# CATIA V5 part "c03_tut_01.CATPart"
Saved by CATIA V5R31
Part number: c03tut1
Bounding box of the stored display mesh (mm): x -1 to 1, y -100 to 100, z -100 to 100
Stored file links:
  D:\PROJECTS\Project 2021\US EDITION\CATIA V5 6R 2021\Resources\Tutorial Files\c03_catia_v5_6r2021_tut\c03_tut_01.CATPart
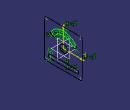
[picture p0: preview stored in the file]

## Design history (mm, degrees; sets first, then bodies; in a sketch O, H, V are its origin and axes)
Body1 (main body)
  Sketch1 on yz-plane, origin (0, 0, 0), H (0, 1, 0), V (0, 0, 1)
    line L1 (100, 90) -> (100, -90)
    line L2 (90, -100) -> (-90, -100)
    line L3 (-100, -90) -> (-100, 90)
    line L4 (-90, 100) -> (90, 100)
    arc A1 centre (90, 90) radius 10 from (100, 90) to (90, 100) ccw
    arc A2 centre (-90, 90) radius 10 from (-100, 90) to (-90, 100) cw
    arc A3 centre (90, -90) radius 10 from (100, -90) to (90, -100) cw
    arc A4 centre (-90, -90) radius 10 from (-90, -100) to (-100, -90) cw
    circle A5 centre (0, 0) radius 20
    construction line L5 (-70, -70) -> (70, -70)
    line L6 (-70, -60) -> (70, -60)
    line L7 (70, -80) -> (-70, -80)
    arc A6 centre (70, -70) radius 10 from (70, -60) to (70, -80) cw
    arc A7 centre (-70, -70) radius 10 from (-70, -80) to (-70, -60) cw
    construction arc A8 centre (0, 0) radius 70 from (57.3406, 40.1504) to (-57.3406, 40.1504) ccw
    construction line L8 (0, 0) -> (57.3406, 40.1504)
    construction line L9 (0, 0) -> (-57.3406, 40.1504)
    arc A9 centre (57.3406, 40.1504) radius 10 from (65.5322, 45.8861) to (49.1491, 34.4146) cw
    arc A10 centre (-57.3406, 40.1504) radius 10 from (-49.1491, 34.4146) to (-65.5322, 45.8861) cw
    arc A11 centre (0, 0) radius 60 from (49.1491, 34.4146) to (-49.1491, 34.4146) ccw
    arc A12 centre (0, 0) radius 80 from (-65.5322, 45.8861) to (65.5322, 45.8861) cw
    radius A1 = 10
    radius A2 = 10
    radius A3 = 10
    radius A4 = 10
    distance L5 L6 = 10
    radius A8 = 70
    angle L8 L9 = 110
    radius A10 = 10
    vertical: L1 V, L3 V
    horizontal: L2 H, L4 H, L5 H
    equidistance: L1 L3 O, L2 L4 O
    tangency: A1 L1, A1 L4, A2 L3, A2 L4, A3 L1, A3 L2, A4 L2, A4 L3, A6 L6, A7 L6, A6 L7, A7 L7, A11 A10, A10 A12, A12 A9, A9 A11
    concentricity: A11 O, A12 O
